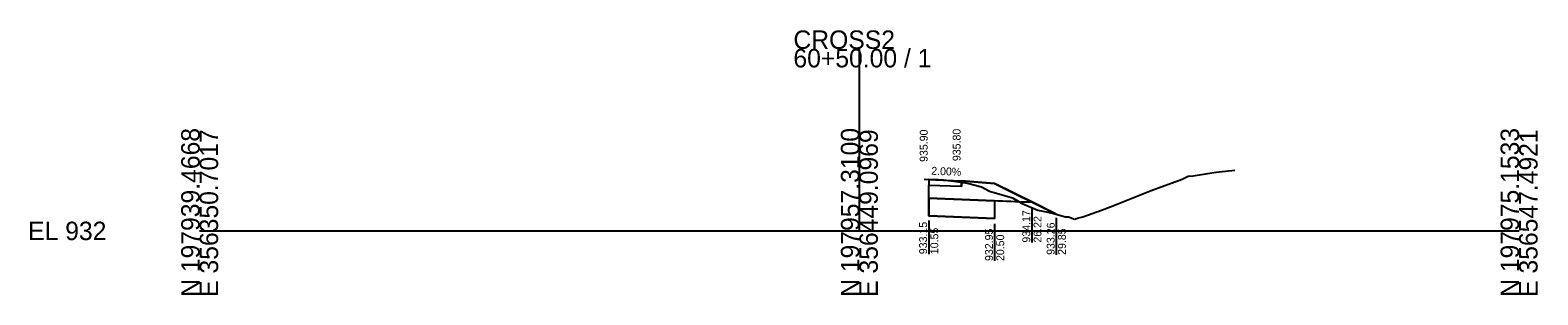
# Model space of a CAD drawing. Extents: x -26 to 203, y -10 to 14021.
# Drawn here: x -25.7 to 202.8, y 1490.3 to 1530.4 of the extents above; entities that cross this region are included whole.
import ezdxf

# ---------------------------------------------------------------- set-up
doc = ezdxf.new("R2010")
doc.units = 0
for name, color, linetype in [('Default', 7, 'Continuous'), ('P_E_XS_Ground', 7, 'Continuous'), ('P_XS', 7, 'Continuous'), ('P_XS_EAR_CommonGrnd', 7, 'Continuous'), ('P_XS_Lane', 7, 'Continuous'), ('P_XS_Rock', 7, 'Continuous')]:
    doc.layers.add(name, color=color, linetype=linetype)

msp = doc.modelspace()

# ---------------------------------------------------------------- linework, layer by layer
at = {"layer": 'Default'}
for p, q in [((100, 1500), (100, 1527.59)), ((0, 1500), (100, 1500)), ((100, 1500), (200, 1500))]:
    msp.add_line(p, q, dxfattribs=at)
at = {"layer": 'P_E_XS_Ground'}
for p, q in [((149.82, 1508.3), (150.61, 1508.37)), ((150.61, 1508.37), (153.73, 1508.85)), ((153.73, 1508.85), (154.52, 1508.94)), ((154.52, 1508.94), (156.89, 1509.2)), ((109.83, 1507.83), (111.56, 1507.75)), ((111.56, 1507.75), (112.6, 1507.73)), ((112.6, 1507.73), (114.67, 1507.47)), ((114.67, 1507.47), (116.05, 1507.31)), ((116.05, 1507.31), (116.59, 1507.17)), ((116.59, 1507.17), (118.51, 1506.68)), ((118.51, 1506.68), (119.7, 1506.05)), ((119.7, 1506.05), (123.21, 1504.99)), ((141.22, 1504.91), (144.22, 1506.13)), ((144.22, 1506.13), (148.91, 1507.86)), ((148.91, 1507.86), (149.82, 1508.3)), ((123.21, 1504.99), (124.68, 1504.17)), ((124.68, 1504.17), (127.06, 1503.13)), ((138.16, 1503.69), (141.22, 1504.91)), ((127.06, 1503.13), (128.54, 1502.86)), ((128.54, 1502.86), (129.42, 1502.66)), ((129.42, 1502.66), (131.24, 1502.11)), ((131.24, 1502.11), (131.69, 1502.12)), ((131.69, 1502.12), (132.62, 1501.78)), ((132.62, 1501.78), (133.06, 1501.93)), ((133.06, 1501.93), (133.85, 1502.13)), ((133.85, 1502.13), (136.69, 1503.12)), ((136.69, 1503.12), (138.16, 1503.69))]:
    msp.add_line(p, q, dxfattribs=at)
at = {"layer": 'P_XS'}
for p, q in [((110.55, 1507.8), (110.55, 1506.96)), ((110.55, 1506.96), (115.5, 1506.77)), ((110.55, 1504.96), (110.55, 1506.96)), ((115.5, 1507.6), (115.5, 1506.77)), ((110.55, 1504.96), (126.22, 1504.34)), ((110.55, 1504.96), (110.55, 1502.3)), ((120.5, 1504.57), (120.5, 1501.9)), ((110.55, 1502.3), (120.5, 1501.9))]:
    msp.add_line(p, q, dxfattribs=at)
at = {"layer": 'P_XS_EAR_CommonGrnd'}
for points in [[(110.55, 1506.96), (115.5, 1506.77), (115.5, 1507.37), (114.67, 1507.47), (112.74, 1507.71), (111.93, 1507.74), (111.56, 1507.75), (110.55, 1507.8)], [(110.55, 1507.8), (111.93, 1507.74), (111.56, 1507.75)], [(118.51, 1506.68), (119.7, 1506.05), (123.21, 1504.99), (124.23, 1504.42), (120.5, 1504.57), (110.55, 1504.96), (110.55, 1506.96), (115.5, 1506.77), (115.5, 1507.37), (116.05, 1507.31), (116.59, 1507.17)], [(111.93, 1507.74), (112.6, 1507.73), (112.74, 1507.71)], [(112.74, 1507.71), (115.5, 1507.6), (115.5, 1507.37), (114.67, 1507.47)], [(118.51, 1506.68), (119.7, 1506.05), (123.21, 1504.99), (124.23, 1504.42), (126.22, 1504.34), (120.5, 1507.2), (115.5, 1507.6), (115.5, 1507.37), (116.05, 1507.31), (116.59, 1507.17)], [(110.55, 1504.96), (120.5, 1504.57), (120.5, 1501.9), (110.55, 1502.3)], [(127.06, 1503.13), (128.54, 1502.86), (129.42, 1502.66), (129.85, 1502.53), (126.22, 1504.34), (124.23, 1504.42), (124.68, 1504.17)]]:
    msp.add_lwpolyline(points, close=True, dxfattribs=at)
at = {"layer": 'P_XS_Lane'}
for p, q in [((110.55, 1507.8), (115.5, 1507.6)), ((115.5, 1507.6), (120.5, 1507.2)), ((120.5, 1507.2), (129.85, 1502.53))]:
    msp.add_line(p, q, dxfattribs=at)
at = {"layer": 'P_XS_Rock'}
for p, q in [((110.51, 1501.57), (110.51, 1496.47)), ((126.15, 1503.33), (126.15, 1498.23)), ((129.85, 1501.97), (129.85, 1496.37)), ((120.5, 1501.06), (120.5, 1495.44))]:
    msp.add_line(p, q, dxfattribs=at)

# ---------------------------------------------------------------- texts
at = {"layer": 'Default'}
for s, p in [('CROSS2', (90, 1527.59)), ('60+50.00 / 1', (90, 1524.79)), ('EL 932', (-26, 1498.6))]:
    msp.add_text(s, height=2.8, dxfattribs=at).set_placement(p)
for s, p in [('N 197939.4668', (0, 1490)), ('E 356350.7017', (2.8, 1490)), ('N 197957.3100', (100, 1490)), ('E 356449.0969', (102.8, 1490)), ('N 197975.1533', (200, 1490)), ('E 356547.4921', (202.8, 1490))]:
    msp.add_text(s, height=2.8, rotation=90, dxfattribs=at).set_placement(p)
at = {"layer": 'P_XS_Rock'}
for s, rotation, p in [('935.90', 90, (110.35, 1510.46)), ('935.80', 90, (115.34, 1510.58)), ('2.00%', 357.7094, (110.87, 1508.52)), ('934.17', 90, (125.9, 1498.23)), ('26.22', 90, (127.6, 1498.23)), ('933.15', 90, (110.26, 1496.47)), ('10.55', 90, (111.96, 1496.47)), ('932.95', 90, (120.25, 1495.44)), ('20.50', 90, (121.95, 1495.44)), ('933.26', 90, (129.6, 1496.37)), ('29.85', 90, (131.3, 1496.37))]:
    msp.add_text(s, height=1.2, rotation=rotation, dxfattribs=at).set_placement(p)

doc.saveas('drawing.dxf')
